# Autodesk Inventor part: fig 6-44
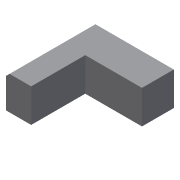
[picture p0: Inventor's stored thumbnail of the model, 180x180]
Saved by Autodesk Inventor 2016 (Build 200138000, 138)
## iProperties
Created: 2010-08
Part Number: fig 6-44
Document SubType Name: Modeling
Designer: CADSoft
Density: 1 g/cm^3
Material: Generic
Appearance: Default
Author: CADSoft
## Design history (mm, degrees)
sketch "Sketch1"
  geometry: L1 (-33.983, 0)-(-48.97, 0); L2 (-48.97, 0)-(-48.97, 51.503); L3 (-48.97, 51.503)-(0, 51.503); L4 (0, 51.503)-(0, 32.411); L5 (-33.983, 0)-(-33.983, 32.411); L6 (-33.983, 32.411)-(0, 32.411); 1 further point
  constraints: 12 end point, 3 parallel, 2 perpendicular, 1 horizontal
extrude "Extrusion1" new body sketch "Sketch1" distance "d0" = 20; taper "d1" = 0 deg
chamfer "Chamfer1" distance "d2" = 2; stored, may be unused: second distance "d3" = 2, angle "d4" = 45 deg
body "Solid1"
